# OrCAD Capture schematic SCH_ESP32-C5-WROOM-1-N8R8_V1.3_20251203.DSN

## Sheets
1 01_DesignBlock: title: ESP32-C5-WROOM-1-N8R8; rev: V1.3; note: <01_DesignBlock>
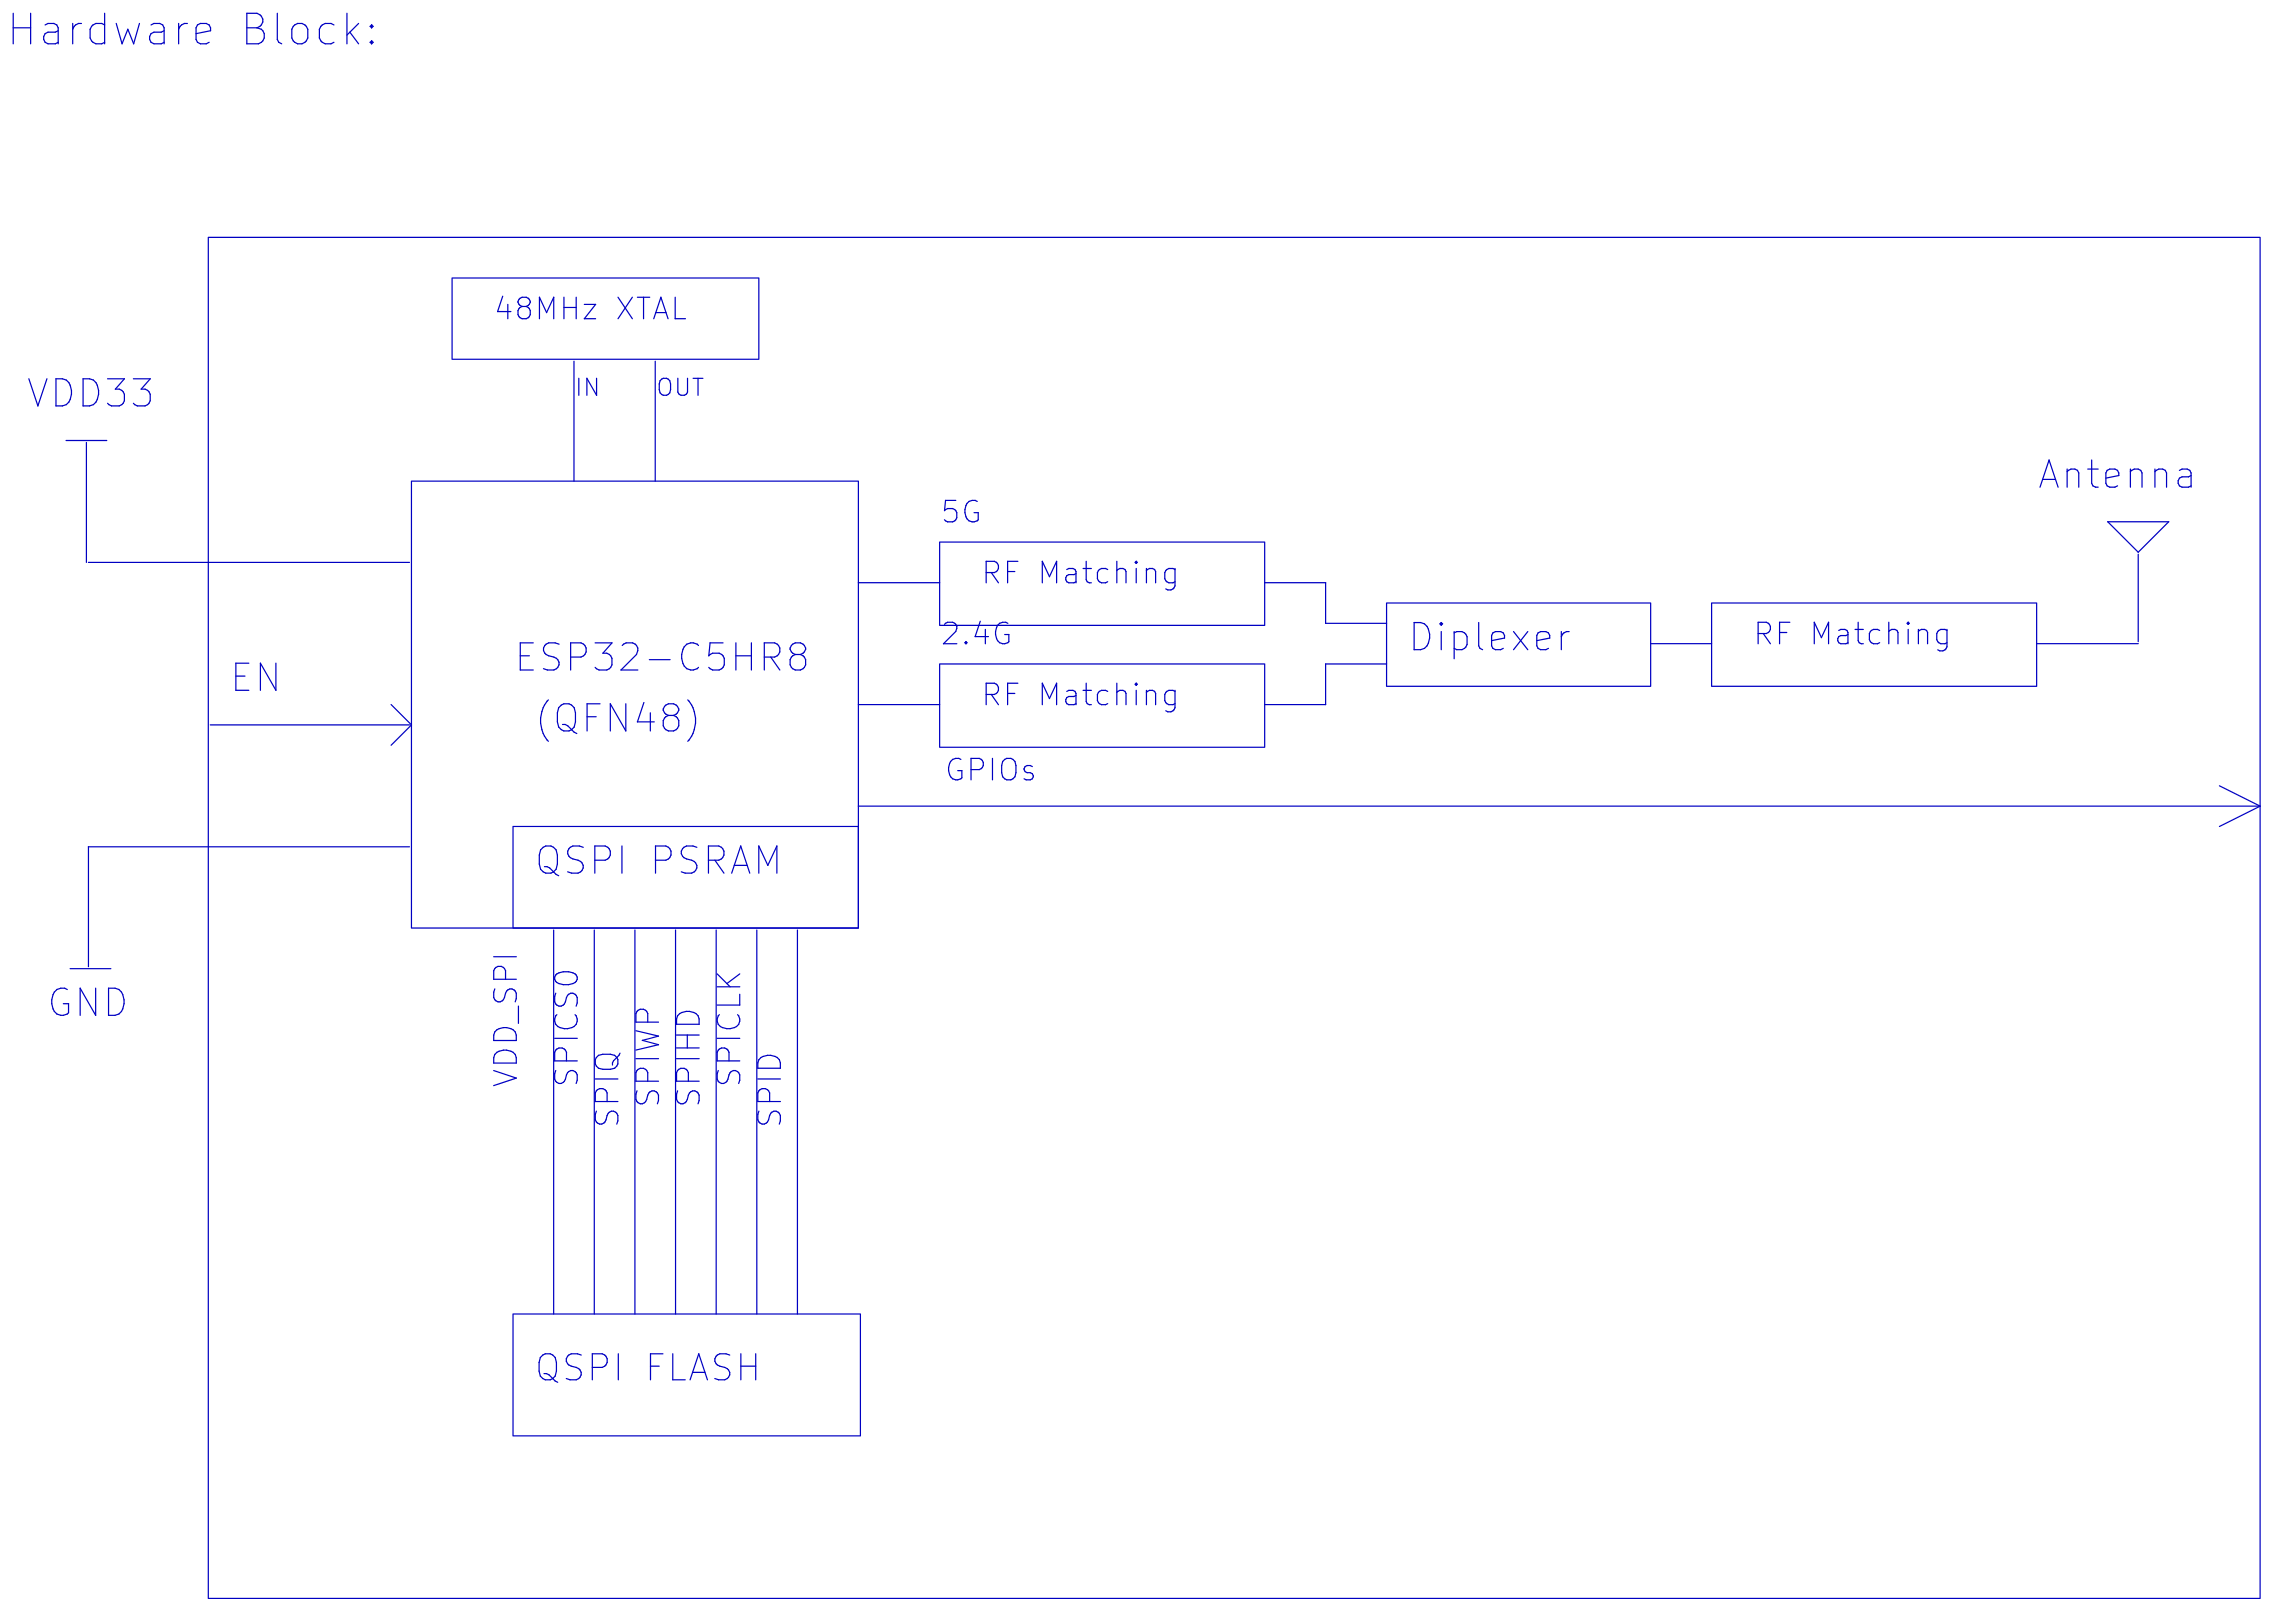
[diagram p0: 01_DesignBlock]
2 02_ESP32-C5-WROOM-1-N8R8: size A3; title: <ESP32-C5-WROOM-1-N8R8>; note: <02_ESP32-C5-WROOM-1-N8R8>
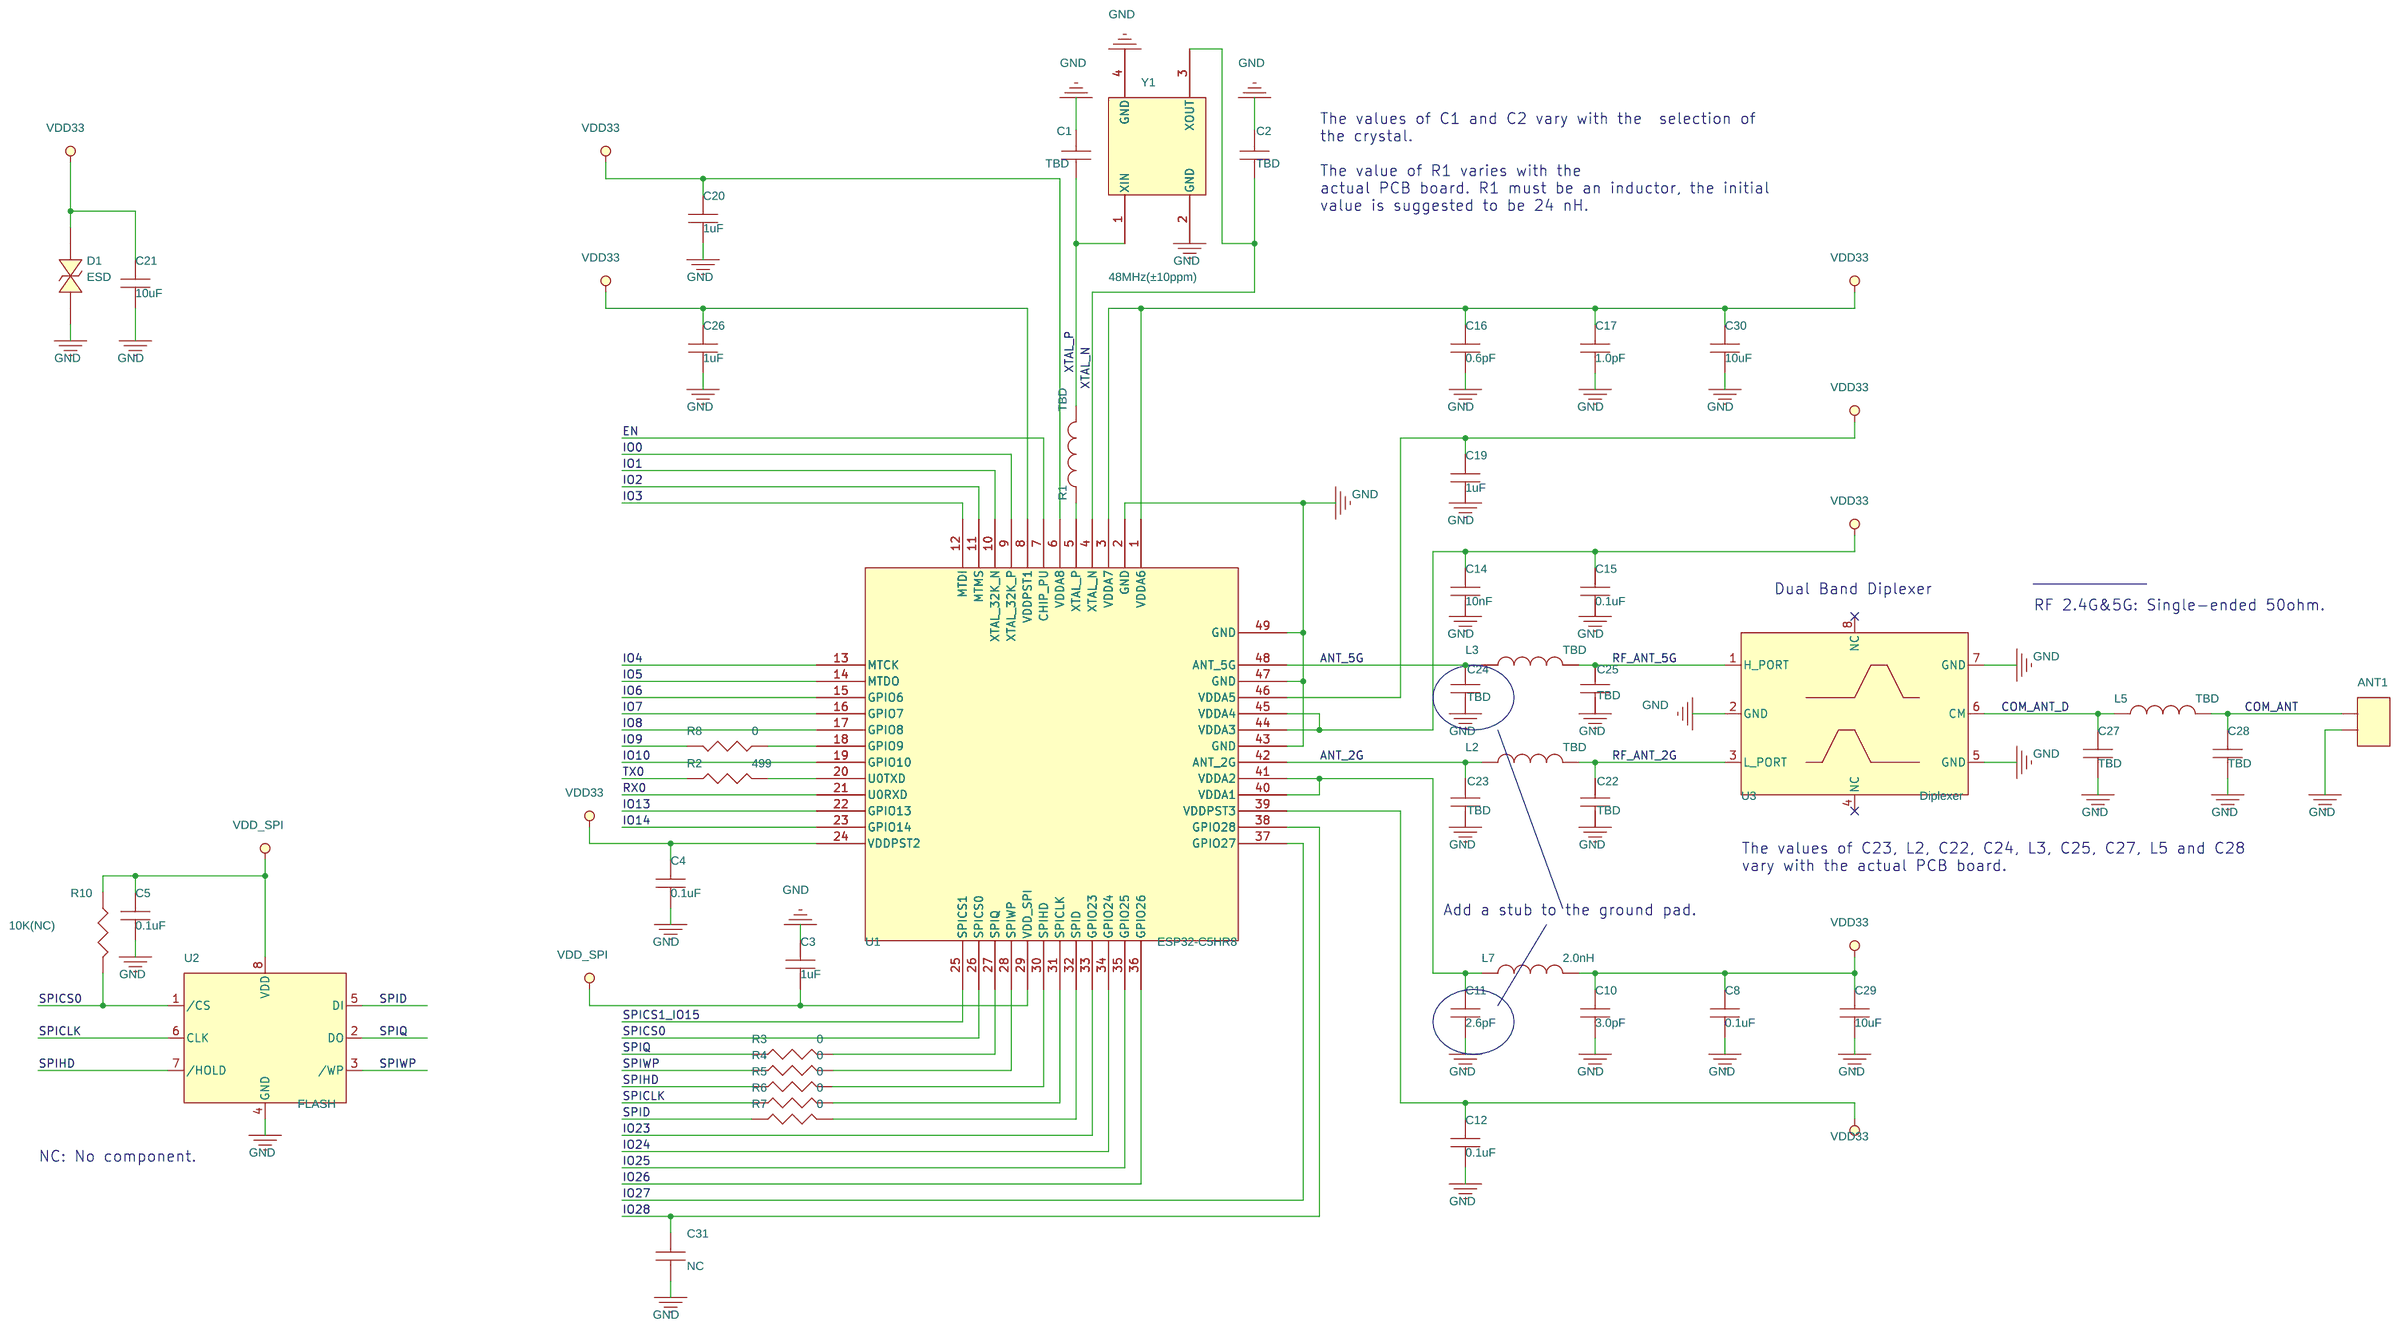
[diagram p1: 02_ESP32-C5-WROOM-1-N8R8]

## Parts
ANT1  ANT  [DB-ANT-TYPEB2]
C1  TBD  [C0201]
C2  TBD  [C0201]
C3  1uF  [C0201]
C4  0.1uF  [C0201]
C5  0.1uF  [C0201]
C8  0.1uF  [C0201]
C10  3.0pF  [C0201]
C11  2.6pF  [C0201]
C12  0.1uF  [C0201]
C14  10nF  [C0201]
C15  0.1uF  [C0201]
C16  0.6pF  [C0201]
C17  1.0pF  [C0201]
C19  1uF  [C0201]
C20  1uF  [C0201]
C21  10uF  [C0402]
C22  TBD  [C0201]
C23  TBD  [C0201]
C24  TBD  [C0201]
C25  TBD  [C0201]
C26  1uF  [C0201]
C27  TBD  [C0201]
C28  TBD  [C0201]
C29  10uF  [C0402]
C30  10uF  [C0402]
C31  NC  [C0201]
D1  ESD  [SOD882]
L2  TBD  [L0201]
L3  TBD  [L0201]
L5  TBD  [L0201]
L7  2.0nH  [L0201]
R1  TBD  [R0201]
R2  499  [R0201]
R3  0  [R0201]
R4  0  [R0201]
R5  0  [R0201]
R6  0  [R0201]
R7  0  [R0201]
R8  0  [R0201]
R10  10K(NC)  [R0201]
U1  ESP32-C5HR8  [QFN48_0P4_6_E4P7]
U2  FLASH  [SOP8_1P27_6P6]
U3  Diplexer  [DIPLEXER8_0P5_1P6X0P8]
Y1  48MHz(±10ppm)  [XTAL2016]

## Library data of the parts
ANT1 = CON2X1
C1 C2 C22-C25 C27 C28 C31 = CAPACITOR
C3 C19 C20 C26 = CAPACITOR: CODE12: ES01.1.1.105.2.7.1.00; Part Number: ES01111052710000; Part Type: Capacitor
C4 C5 C8 C12 C15 = CAPACITOR: CODE12: ES01.1.1.104.2.6.1.00; Part Number: ES01111042610000; Part Type: Capacitor
C10 = CAPACITOR: CODE12: ES01.1.1.3R0.6.2.2.00; Part Number: ES01113R06220000; Part Type: Capacitor
C11 C17 = CAPACITOR: CODE12: ES01.1.1.1R0.6.2.2.00; Part Number: ES01111R06220000; Part Type: Capacitor
C14 = CAPACITOR: CODE12: ES01.1.1.103.3.6.2.00; Part Number: ES01111033620000; Part Type: Capacitor
C16 = CAPACITOR: CODE12: ES01.1.1.R60.6.2.2.00; Part Number: ES0111R606220000; Part Type: Capacitor
C21 C29 C30 = CAPACITOR: CODE12: ES01.1.2.106.2.7.1.00; Part Number: ES01121062710000; Part Type: Capacitor
D1 = DIODE_BI_DIR: CODE12: ES06.1.1.3.01.00000; Part Number: ES06113010000000; Part Type: Diode
L2 L3 L5 R1 = INDUCTOR
L7 = INDUCTOR: CODE12: ES02.1.1.2N0.0.2.001; Part Number: ES02112N00200100; Part Type: Inductor
R2 = RESISTOR: CODE12: ES03.1.1.4990.1.000; Part Number: ES03114990100000; Part Type: Resistor
R3-R8 = RESISTOR: CODE12: ES03.1.1.0000.1.000; Part Number: ES03110000100000; Part Type: Resistor
R10 = RESISTOR: CODE12: ES03.1.1.4100.1.000; Part Number: ES03114100100002; Part Type: Resistor
U1 = ESP32-C5_QFN48
U2 = FLASH: CODE12: ES05.0.1.02.3.4.1.000; Part Number: ES05010234100000; Part Type: Memory ICs
U3 = LFD182G45DCHD481
Y1 = XTAL_4P

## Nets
GND: ANT1.2 C1.2 C2.2 C3.1 C4.2 C5.2 C8.2 C10.2 C11.2 C12.2 C14.2 C15.2 C16.2 C17.2 C19.2 C20.2 C21.2 C22.2 C23.2 C24.2 C25.2 C26.2 C27.2 C28.2 C29.2 C30.2 C31.2 D1.1 U1.2(GND) U1.43(GND) U1.47(GND) U1.49(GND) U2.4(GND) U3.2(GND) U3.5(GND) U3.7(GND) Y1.2(GND) Y1.4(GND)
VDD33: C4.1 C8.1 C10.1 C12.1 C14.1 C15.1 C16.1 C17.1 C19.1 C20.1 C21.1 C26.1 C29.1 C30.1 D1.2 L7.2 U1.1(VDDA6) U1.3(VDDA7) U1.6(VDDA8) U1.8(VDDPST1) U1.24(VDDPST2) U1.39(VDDPST3) U1.44(VDDA3) U1.45(VDDA4) U1.46(VDDA5)
VDD_SPI: C3.2 C5.1 R10.1 U1.29(VDD_SPI) U2.8(VDD)
ANT_2G: C23.1 L2.1 U1.42(ANT_2G)
ANT_5G: C24.1 L3.1 U1.48(ANT_5G)
COM_ANT: ANT1.1 C28.1 L5.1
COM_ANT_D: C27.1 L5.2 U3.6(CM)
EN: U1.7(CHIP_PU)
IO0: U1.9(XTAL_32K_P)
IO1: U1.10(XTAL_32K_N)
IO2: U1.11(MTMS)
IO3: U1.12(MTDI)
IO4: U1.13(MTCK)
IO5: U1.14(MTDO)
IO6: U1.15(GPIO6)
IO7: U1.16(GPIO7)
IO8: U1.17(GPIO8)
IO9: R8.2
IO10: U1.19(GPIO10)
IO13: U1.22(GPIO13)
IO14: U1.23(GPIO14)
IO23: U1.33(GPIO23)
IO24: U1.34(GPIO24)
IO25: U1.35(GPIO25)
IO26: U1.36(GPIO26)
IO27: U1.37(GPIO27)
IO28: C31.1 U1.38(GPIO28)
RF_ANT_2G: C22.1 L2.2 U3.3(L_PORT)
RF_ANT_5G: C25.1 L3.2 U3.1(H_PORT)
RX0: U1.21(U0RXD)
SPICLK: R6.1 U2.6(CLK)
SPICS0: R10.2 U1.26(SPICS0) U2.1(/CS)
SPICS1_IO15: U1.25(SPICS1)
SPID: R7.1 U2.5(DI)
SPIHD: R5.1 U2.7(/HOLD)
SPIQ: R3.1 U2.2(DO)
SPIWP: R4.1 U2.3(/WP)
TX0: R2.1
XTAL_N: C2.1 U1.4(XTAL_N) Y1.3(XOUT)
XTAL_P: C1.1 R1.1 Y1.1(XIN)
N17787760: R2.2 U1.20(U0TXD)
N17787816: R1.2 U1.5(XTAL_P)
N17788259: R3.2 U1.27(SPIQ)
N17788269: R4.2 U1.28(SPIWP)
N17788276: R5.2 U1.30(SPIHD)
N17788283: R6.2 U1.31(SPICLK)
N17788296: R7.2 U1.32(SPID)
N17788310: C11.1 L7.1 U1.40(VDDA1) U1.41(VDDA2)
N17796174: R8.1 U1.18(GPIO9)

Not connected (* = marked no-connect by the designer): U3 4(NC)* 8(NC)*

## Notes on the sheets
sheet 1
- Hardware Block:
- 48MHz XTAL
- VDD33
- IN
- OUT
- Antenna
- 5G
- RF Matching
- 2.4G
- Diplexer
- RF Matching
- ESP32-C5HR8
- EN
- RF Matching
- (QFN48)
- GPIOs
- QSPI PSRAM
- GND
- VDD_SPI
- SPICS0
- SPICLK
- SPIWP
- SPIHD
- SPIQ
- SPID
- QSPI FLASH
sheet 2
- The values of C1 and C2 vary with the  selection of
  the crystal.
  The value of R1 varies with the
  actual PCB board. R1 must be an inductor, the initial
  value is suggested to be 24 nH.
- Dual Band Diplexer
- RF 2.4G&5G: Single-ended 50ohm.
- The values of C23, L2, C22, C24, L3, C25, C27, L5 and C28
  vary with the actual PCB board.
- Add a stub to the ground pad.
- NC: No component.
